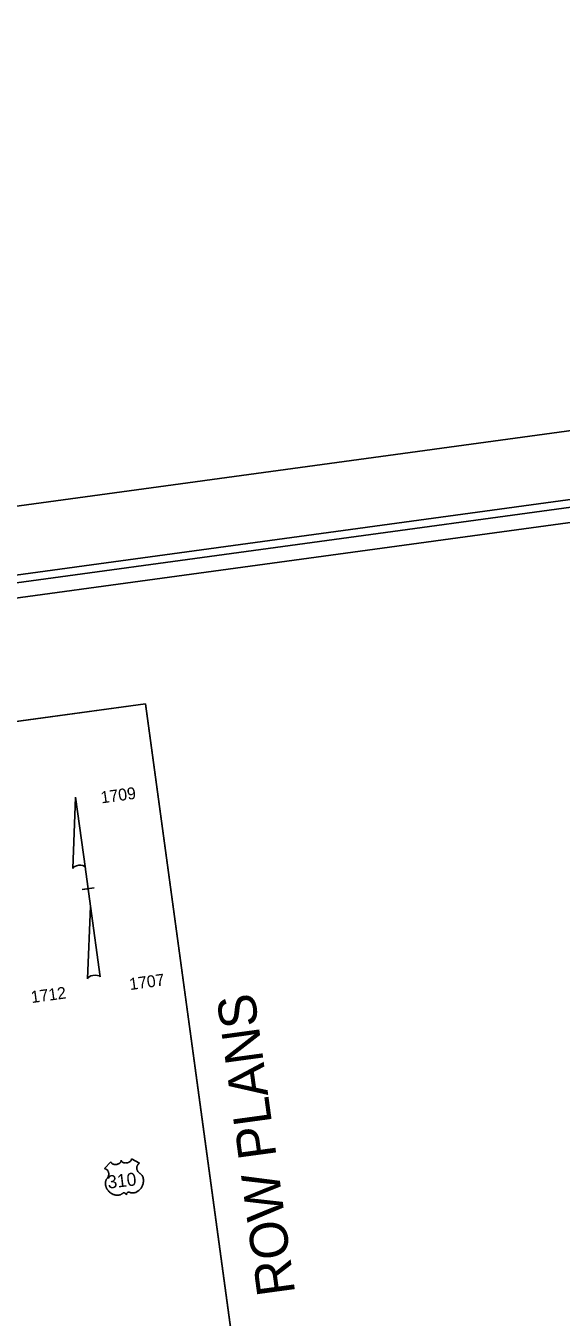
# Model space of a CAD drawing. Extents: x 2110583 to 2112764, y 580993 to 582575.
# Drawn here: x 2111195 to 2111407, y 582064 to 582575 of the extents above; entities that cross this region are included whole.
import ezdxf

# ---------------------------------------------------------------- set-up
doc = ezdxf.new("R2010")
doc.units = 0
for name, color, linetype in [('Default', 7, 'Continuous'), ('Prop North Arrow for Plan Sheets CELL', 7, 'Continuous'), ('Scratch_Level_0', 7, 'Continuous'), ('Sheet Plot Border Inside CELL', 7, 'Continuous'), ('Sheet Plot Border Outside CELL', 7, 'Continuous'), ('Sheet Title CELL', 7, 'Continuous')]:
    doc.layers.add(name, color=color, linetype=linetype)

msp = doc.modelspace()

# ---------------------------------------------------------------- linework, layer by layer
at = {"layer": 'Default'}
for p, q in [((2111226.63, 582122.35), (2111229.12, 582125.04)), ((2111229.14, 582124.92), (2111229.12, 582125.04)), ((2111229.14, 582124.92), (2111229.19, 582124.79)), ((2111229.19, 582124.79), (2111229.23, 582124.72)), ((2111229.23, 582124.72), (2111229.31, 582124.59)), ((2111229.31, 582124.59), (2111229.44, 582124.45)), ((2111229.44, 582124.45), (2111229.62, 582124.31)), ((2111229.62, 582124.31), (2111229.81, 582124.2)), ((2111229.81, 582124.2), (2111229.93, 582124.14)), ((2111229.93, 582124.14), (2111230.14, 582124.06)), ((2111230.14, 582124.06), (2111230.37, 582124.01)), ((2111230.37, 582124.01), (2111230.63, 582123.97)), ((2111230.63, 582123.97), (2111230.89, 582123.96)), ((2111230.89, 582123.96), (2111231.16, 582123.97)), ((2111231.16, 582123.97), (2111231.43, 582124.01)), ((2111231.43, 582124.01), (2111231.72, 582124.07)), ((2111231.72, 582124.07), (2111232.03, 582124.18)), ((2111232.03, 582124.18), (2111232.18, 582124.24)), ((2111232.18, 582124.24), (2111232.33, 582124.33)), ((2111232.33, 582124.33), (2111232.48, 582124.41)), ((2111232.48, 582124.41), (2111232.63, 582124.53)), ((2111232.63, 582124.53), (2111232.76, 582124.64)), ((2111232.76, 582124.64), (2111232.85, 582124.73)), ((2111232.85, 582124.73), (2111232.98, 582124.9)), ((2111232.98, 582124.9), (2111233.08, 582125.06)), ((2111233.08, 582125.06), (2111233.11, 582125.16)), ((2111233.11, 582125.16), (2111233.15, 582125.24)), ((2111233.15, 582125.24), (2111233.18, 582125.42)), ((2111233.18, 582125.5), (2111233.17, 582125.66)), ((2111233.17, 582125.66), (2111233.2, 582125.53)), ((2111233.18, 582125.42), (2111233.18, 582125.5)), ((2111233.2, 582125.53), (2111233.23, 582125.45)), ((2111233.23, 582125.45), (2111233.26, 582125.37)), ((2111233.26, 582125.37), (2111233.31, 582125.29)), ((2111233.31, 582125.29), (2111233.39, 582125.18)), ((2111233.39, 582125.18), (2111233.47, 582125.09)), ((2111233.47, 582125.09), (2111233.62, 582124.96)), ((2111233.62, 582124.96), (2111233.71, 582124.9)), ((2111233.71, 582124.9), (2111233.79, 582124.85)), ((2111233.79, 582124.85), (2111234, 582124.75)), ((2111234, 582124.75), (2111234.24, 582124.67)), ((2111234.24, 582124.67), (2111234.36, 582124.64)), ((2111234.36, 582124.64), (2111234.48, 582124.61)), ((2111234.48, 582124.61), (2111234.63, 582124.59)), ((2111234.63, 582124.59), (2111234.79, 582124.58)), ((2111234.79, 582124.58), (2111234.94, 582124.57)), ((2111234.94, 582124.57), (2111235.09, 582124.58)), ((2111235.09, 582124.58), (2111235.25, 582124.59)), ((2111235.25, 582124.59), (2111235.37, 582124.6)), ((2111235.37, 582124.6), (2111235.53, 582124.63)), ((2111235.53, 582124.63), (2111235.67, 582124.66)), ((2111235.67, 582124.66), (2111235.81, 582124.7)), ((2111235.81, 582124.7), (2111235.97, 582124.75)), ((2111235.97, 582124.75), (2111236.09, 582124.8)), ((2111236.09, 582124.8), (2111236.26, 582124.87)), ((2111236.26, 582124.87), (2111236.4, 582124.95)), ((2111236.4, 582124.95), (2111236.53, 582125.02)), ((2111236.53, 582125.02), (2111236.69, 582125.14)), ((2111236.69, 582125.14), (2111236.82, 582125.25)), ((2111236.82, 582125.25), (2111236.91, 582125.35)), ((2111236.91, 582125.35), (2111237.02, 582125.49)), ((2111237.02, 582125.49), (2111237.11, 582125.64)), ((2111237.11, 582125.64), (2111237.17, 582125.75)), ((2111237.17, 582125.75), (2111237.2, 582125.86)), ((2111237.2, 582125.86), (2111237.23, 582125.97)), ((2111237.23, 582126.28), (2111240.41, 582124.45)), ((2111237.24, 582126.19), (2111237.23, 582126.28)), ((2111237.23, 582125.97), (2111237.24, 582126.09)), ((2111237.24, 582126.09), (2111237.24, 582126.19)), ((2111239.37, 582122.8), (2111239.36, 582122.67)), ((2111239.36, 582122.67), (2111239.36, 582122.41)), ((2111239.39, 582122.95), (2111239.37, 582122.8)), ((2111239.44, 582123.19), (2111239.39, 582122.95)), ((2111239.48, 582123.3), (2111239.44, 582123.19)), ((2111239.53, 582123.44), (2111239.48, 582123.3)), ((2111239.59, 582123.57), (2111239.53, 582123.44)), ((2111239.65, 582123.69), (2111239.59, 582123.57)), ((2111239.71, 582123.78), (2111239.65, 582123.69)), ((2111239.77, 582123.88), (2111239.71, 582123.78)), ((2111239.84, 582123.97), (2111239.77, 582123.88)), ((2111239.91, 582124.06), (2111239.84, 582123.97)), ((2111240.09, 582124.22), (2111239.91, 582124.06)), ((2111240.2, 582124.31), (2111240.09, 582124.22)), ((2111240.34, 582124.41), (2111240.2, 582124.31)), ((2111240.41, 582124.45), (2111240.34, 582124.41)), ((2111226.72, 582122.33), (2111226.63, 582122.35)), ((2111226.87, 582122.28), (2111226.72, 582122.33)), ((2111227.02, 582122.22), (2111226.87, 582122.28)), ((2111227.15, 582122.15), (2111227.02, 582122.22)), ((2111227.05, 582117.42), (2111227.12, 582117.62)), ((2111227.12, 582117.62), (2111227.19, 582117.79)), ((2111227.29, 582122.08), (2111227.15, 582122.15)), ((2111227.19, 582117.79), (2111227.27, 582117.98)), ((2111227.27, 582117.98), (2111227.36, 582118.14)), ((2111227.43, 582121.97), (2111227.29, 582122.08)), ((2111227.36, 582118.14), (2111227.48, 582118.32)), ((2111227.58, 582121.85), (2111227.43, 582121.97)), ((2111227.48, 582118.32), (2111227.61, 582118.48)), ((2111227.72, 582121.69), (2111227.58, 582121.85)), ((2111227.61, 582118.48), (2111227.73, 582118.62)), ((2111227.86, 582121.52), (2111227.72, 582121.69)), ((2111227.73, 582118.62), (2111227.87, 582118.8)), ((2111227.95, 582121.4), (2111227.86, 582121.52)), ((2111227.87, 582118.8), (2111227.94, 582118.91)), ((2111227.94, 582118.91), (2111228.02, 582119.06)), ((2111228.04, 582121.22), (2111227.95, 582121.4)), ((2111228.02, 582119.06), (2111228.09, 582119.2)), ((2111228.11, 582121.06), (2111228.04, 582121.22)), ((2111228.09, 582119.2), (2111228.14, 582119.32)), ((2111228.18, 582120.88), (2111228.11, 582121.06)), ((2111228.14, 582119.32), (2111228.2, 582119.5)), ((2111228.23, 582120.69), (2111228.18, 582120.88)), ((2111228.2, 582119.5), (2111228.23, 582119.63)), ((2111228.26, 582120.52), (2111228.23, 582120.69)), ((2111228.23, 582119.63), (2111228.27, 582119.83)), ((2111228.28, 582120.32), (2111228.26, 582120.52)), ((2111228.27, 582119.83), (2111228.28, 582119.97)), ((2111228.29, 582120.15), (2111228.28, 582120.32)), ((2111228.28, 582119.97), (2111228.29, 582120.15)), ((2111239.36, 582122.41), (2111239.37, 582122.29)), ((2111239.37, 582122.29), (2111239.39, 582122.17)), ((2111239.39, 582122.17), (2111239.42, 582122.05)), ((2111239.42, 582122.05), (2111239.45, 582121.93)), ((2111239.45, 582121.93), (2111239.49, 582121.8)), ((2111239.49, 582121.8), (2111239.52, 582121.7)), ((2111239.52, 582121.7), (2111239.58, 582121.57)), ((2111239.58, 582121.57), (2111239.65, 582121.42)), ((2111239.65, 582121.42), (2111239.74, 582121.27)), ((2111239.74, 582121.27), (2111239.91, 582121.05)), ((2111239.91, 582121.05), (2111240.11, 582120.82)), ((2111240.11, 582120.82), (2111240.25, 582120.7)), ((2111240.25, 582120.7), (2111240.39, 582120.6)), ((2111240.39, 582120.6), (2111240.58, 582120.48)), ((2111240.58, 582120.48), (2111240.69, 582120.41)), ((2111240.69, 582120.41), (2111240.82, 582120.31)), ((2111240.82, 582120.31), (2111241.03, 582120.13)), ((2111241.03, 582120.13), (2111241.11, 582120.05)), ((2111241.11, 582120.05), (2111241.2, 582119.95)), ((2111241.2, 582119.95), (2111241.29, 582119.85)), ((2111241.29, 582119.85), (2111241.37, 582119.74)), ((2111241.37, 582119.74), (2111241.44, 582119.64)), ((2111241.44, 582119.64), (2111241.58, 582119.41)), ((2111241.58, 582119.41), (2111241.68, 582119.19)), ((2111241.68, 582119.19), (2111241.74, 582119.07)), ((2111241.74, 582119.07), (2111241.83, 582118.8)), ((2111241.83, 582118.8), (2111241.87, 582118.66)), ((2111241.87, 582118.66), (2111241.94, 582118.4)), ((2111241.94, 582118.4), (2111241.99, 582118.07)), ((2111241.99, 582118.07), (2111242.01, 582117.75)), ((2111242.01, 582117.75), (2111242, 582117.38)), ((2111226.94, 582116.67), (2111226.95, 582116.88)), ((2111226.94, 582116.42), (2111226.94, 582116.67)), ((2111226.95, 582116.2), (2111226.94, 582116.42)), ((2111226.95, 582116.88), (2111226.97, 582117.03)), ((2111226.97, 582116.01), (2111226.95, 582116.2)), ((2111226.97, 582117.03), (2111227, 582117.21)), ((2111227.01, 582115.78), (2111226.97, 582116.01)), ((2111227, 582117.21), (2111227.05, 582117.42)), ((2111227.06, 582115.53), (2111227.01, 582115.78)), ((2111227.13, 582115.3), (2111227.06, 582115.53)), ((2111227.19, 582115.13), (2111227.13, 582115.3)), ((2111227.28, 582114.9), (2111227.19, 582115.13)), ((2111227.34, 582114.76), (2111227.28, 582114.9)), ((2111227.44, 582114.56), (2111227.34, 582114.76)), ((2111227.56, 582114.34), (2111227.44, 582114.56)), ((2111227.71, 582114.1), (2111227.56, 582114.34)), ((2111227.82, 582113.94), (2111227.71, 582114.1)), ((2111228.01, 582113.69), (2111227.82, 582113.94)), ((2111228.14, 582113.54), (2111228.01, 582113.69)), ((2111228.33, 582113.33), (2111228.14, 582113.54)), ((2111228.63, 582113.04), (2111228.33, 582113.33)), ((2111228.81, 582112.89), (2111228.63, 582113.04)), ((2111229.13, 582112.66), (2111228.81, 582112.89)), ((2111229.33, 582112.52), (2111229.13, 582112.66)), ((2111229.61, 582112.35), (2111229.33, 582112.52)), ((2111233.6, 582112.43), (2111233.46, 582112.32)), ((2111233.72, 582112.53), (2111233.6, 582112.43)), ((2111233.83, 582112.63), (2111233.72, 582112.53)), ((2111233.95, 582112.75), (2111233.83, 582112.63)), ((2111234.04, 582112.78), (2111233.95, 582112.75)), ((2111234.11, 582112.79), (2111234.04, 582112.78)), ((2111234.19, 582112.8), (2111234.11, 582112.79)), ((2111234.3, 582112.79), (2111234.19, 582112.8)), ((2111234.39, 582112.77), (2111234.3, 582112.79)), ((2111234.48, 582112.74), (2111234.39, 582112.77)), ((2111234.61, 582112.69), (2111234.48, 582112.74)), ((2111234.73, 582112.62), (2111234.61, 582112.69)), ((2111234.83, 582112.54), (2111234.73, 582112.62)), ((2111234.95, 582112.44), (2111234.83, 582112.54)), ((2111235.02, 582112.37), (2111234.95, 582112.44)), ((2111235.1, 582112.27), (2111235.02, 582112.37)), ((2111235.37, 582112.49), (2111235.3, 582112.32)), ((2111235.41, 582112.56), (2111235.37, 582112.49)), ((2111235.47, 582112.65), (2111235.41, 582112.56)), ((2111235.55, 582112.75), (2111235.47, 582112.65)), ((2111235.62, 582112.83), (2111235.55, 582112.75)), ((2111235.72, 582112.91), (2111235.62, 582112.83)), ((2111235.79, 582112.97), (2111235.72, 582112.91)), ((2111235.91, 582113.04), (2111235.79, 582112.97)), ((2111236.04, 582113.08), (2111235.91, 582113.04)), ((2111236.17, 582113.1), (2111236.04, 582113.08)), ((2111236.23, 582113.09), (2111236.17, 582113.1)), ((2111236.34, 582113.05), (2111236.23, 582113.09)), ((2111236.72, 582112.89), (2111236.34, 582113.05)), ((2111236.95, 582112.81), (2111236.72, 582112.89)), ((2111237.17, 582112.77), (2111236.95, 582112.81)), ((2111237.4, 582112.73), (2111237.17, 582112.77)), ((2111237.62, 582112.72), (2111237.4, 582112.73)), ((2111237.84, 582112.72), (2111237.62, 582112.72)), ((2111238.06, 582112.74), (2111237.84, 582112.72)), ((2111238.28, 582112.77), (2111238.06, 582112.74)), ((2111238.44, 582112.81), (2111238.28, 582112.77)), ((2111238.61, 582112.85), (2111238.44, 582112.81)), ((2111238.78, 582112.9), (2111238.61, 582112.85)), ((2111238.93, 582112.96), (2111238.78, 582112.9)), ((2111239.33, 582113.14), (2111238.93, 582112.96)), ((2111239.57, 582113.27), (2111239.33, 582113.14)), ((2111239.75, 582113.38), (2111239.57, 582113.27)), ((2111239.95, 582113.53), (2111239.75, 582113.38)), ((2111240.19, 582113.72), (2111239.95, 582113.53)), ((2111240.42, 582113.93), (2111240.19, 582113.72)), ((2111240.59, 582114.1), (2111240.42, 582113.93)), ((2111240.71, 582114.23), (2111240.59, 582114.1)), ((2111240.9, 582114.47), (2111240.71, 582114.23)), ((2111241.04, 582114.66), (2111240.9, 582114.47)), ((2111241.22, 582114.92), (2111241.04, 582114.66)), ((2111241.36, 582115.17), (2111241.22, 582114.92)), ((2111241.48, 582115.39), (2111241.36, 582115.17)), ((2111241.57, 582115.59), (2111241.48, 582115.39)), ((2111241.65, 582115.77), (2111241.57, 582115.59)), ((2111241.75, 582116.07), (2111241.65, 582115.77)), ((2111241.83, 582116.32), (2111241.75, 582116.07)), ((2111241.91, 582116.66), (2111241.83, 582116.32)), ((2111241.95, 582116.89), (2111241.91, 582116.66)), ((2111241.99, 582117.16), (2111241.95, 582116.89)), ((2111242, 582117.38), (2111241.99, 582117.16)), ((2111229.98, 582112.17), (2111229.61, 582112.35)), ((2111230.29, 582112.05), (2111229.98, 582112.17)), ((2111230.48, 582111.99), (2111230.29, 582112.05)), ((2111230.76, 582111.92), (2111230.48, 582111.99)), ((2111230.97, 582111.87), (2111230.76, 582111.92)), ((2111231.18, 582111.84), (2111230.97, 582111.87)), ((2111231.37, 582111.82), (2111231.18, 582111.84)), ((2111231.55, 582111.8), (2111231.37, 582111.82)), ((2111231.77, 582111.8), (2111231.55, 582111.8)), ((2111231.95, 582111.81), (2111231.77, 582111.8)), ((2111232.1, 582111.82), (2111231.95, 582111.81)), ((2111232.26, 582111.85), (2111232.1, 582111.82)), ((2111232.41, 582111.88), (2111232.26, 582111.85)), ((2111232.58, 582111.92), (2111232.41, 582111.88)), ((2111232.73, 582111.96), (2111232.58, 582111.92)), ((2111232.9, 582112.03), (2111232.73, 582111.96)), ((2111233.07, 582112.1), (2111232.9, 582112.03)), ((2111233.22, 582112.18), (2111233.07, 582112.1)), ((2111233.35, 582112.25), (2111233.22, 582112.18)), ((2111233.46, 582112.32), (2111233.35, 582112.25)), ((2111235.17, 582112.16), (2111235.1, 582112.27)), ((2111235.24, 582111.99), (2111235.17, 582112.16)), ((2111235.25, 582112.14), (2111235.24, 582111.99)), ((2111235.27, 582112.24), (2111235.25, 582112.14)), ((2111235.3, 582112.32), (2111235.27, 582112.24))]:
    msp.add_line(p, q, dxfattribs=at)
at = {"layer": 'Prop North Arrow for Plan Sheets CELL'}
for p, q in [((2111214.01, 582241.21), (2111215.13, 582269.44)), ((2111215.16, 582269.45), (2111215.13, 582269.44)), ((2111215.16, 582269.45), (2111215.13, 582269.44)), ((2111215.16, 582269.45), (2111219.03, 582241.01)), ((2111221.04, 582226.26), (2111218.92, 582241.85)), ((2111219.03, 582241.01), (2111218.92, 582241.82)), ((2111217.72, 582232.84), (2111217.69, 582232.83)), ((2111219.83, 582233.13), (2111217.72, 582232.84)), ((2111217.75, 582232.84), (2111222.51, 582233.49)), ((2111221.04, 582226.26), (2111219.89, 582197.48)), ((2111224.87, 582198.28), (2111221.04, 582226.26))]:
    msp.add_line(p, q, dxfattribs=at)
for centre, start_param, end_param in [((2111216.51, 582241.25), 0.216273, 2.908104), ((2111222.43, 582197.73), 0.201214, 3.141479)]:
    msp.add_ellipse(centre, major_axis=(2.52, 0.32), ratio=0.461208, start_param=start_param, end_param=end_param, dxfattribs=at)
at = {"layer": 'Scratch_Level_0'}
msp.add_lwpolyline([(2110909.81, 582260.89), (2111242.78, 582306.33), (2111281.74, 582020.84), (2110948.77, 581975.4)], close=True, dxfattribs=at)
at = {"layer": 'Sheet Plot Border Inside CELL'}
msp.add_lwpolyline([(2110773, 581021.72), (2112754.79, 581292.17), (2112583.51, 582547.28), (2110601.71, 582276.83)], close=True, dxfattribs=at)
at = {"layer": 'Sheet Plot Border Outside CELL'}
msp.add_lwpolyline([(2112585.22, 582574.72), (2110582.61, 582301.43), (2110761.18, 580992.92), (2112763.78, 581266.21)], close=True, dxfattribs=at)
at = {"layer": 'Sheet Title CELL'}
for p, q in [((2110909.81, 582260.89), (2111242.78, 582306.33)), ((2111242.78, 582306.33), (2111289.86, 581961.36))]:
    msp.add_line(p, q, dxfattribs=at)
for points in [[(2112557.18, 582540.6), (2110797.14, 582300.43)], [(2112552.03, 582533.84), (2110863.39, 582303.39)]]:
    msp.add_lwpolyline(points, dxfattribs=at)

# ---------------------------------------------------------------- texts
at = {"layer": 'Default'}
for s, height, rotation, p in [('1709', 4.705, 7.771, (2111225.41, 582266.91)), ('1707', 4.705, 7.771, (2111236.72, 582193.01)), ('1712', 4.705, 7.771, (2111197.78, 582187.87)), ('310', 5.153, 6.7335, (2111228.03, 582114.41))]:
    msp.add_text(s, height=height, rotation=rotation, dxfattribs=at).set_placement(p)
at = {"layer": 'Sheet Title CELL'}
msp.add_text('ROW PLANS', height=15.003, rotation=97.771, dxfattribs=at).set_placement((2111302.09, 582073.03))

doc.saveas('drawing.dxf')
